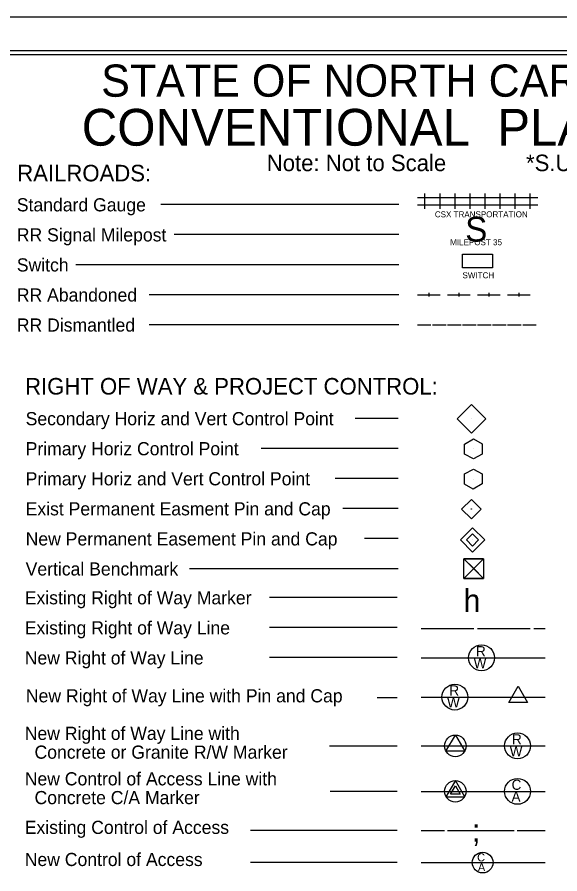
# Model space of a CAD drawing. Extents: x 10000 to 11684, y 10000 to 11100.
# Drawn here: x 10562 to 10923, y 10530 to 11100 of the extents above; entities that cross this region are included whole.
import ezdxf

# ---------------------------------------------------------------- set-up
doc = ezdxf.new("R2010")
doc.units = 0
for name, color, linetype in [('Default', 7, 'Continuous'), ('Prop ROW Permanent Easement CELL', 7, 'Continuous'), ('Sheet Cutting Line CELL', 7, 'Continuous'), ('Sheet Plot Border Inside CELL', 7, 'Continuous'), ('Sheet Plot Border Outside CELL', 7, 'Continuous'), ('Sheet Symbology CELL', 7, 'Continuous')]:
    doc.layers.add(name, color=color, linetype=linetype)

msp = doc.modelspace()

# ---------------------------------------------------------------- linework, layer by layer
at = {"layer": 'Default'}
for p, q in [((10863.87, 10832.65), (10863.87, 10832.65)), ((10865.17, 10812.64), (10865.17, 10812.64)), ((10865.17, 10792.64), (10865.17, 10792.64)), ((10863.9, 10772.61), (10863.9, 10772.61)), ((10865.42, 10733.03), (10865.42, 10733.03))]:
    msp.add_line(p, q, dxfattribs=at)
for points in [[(10854.46, 10832.68), (10863.92, 10842.14), (10873.39, 10832.66), (10863.93, 10823.21)], [(10859.34, 10796.02), (10865.21, 10799.29), (10871.07, 10796.06), (10870.98, 10789.34), (10865.12, 10785.94), (10859.34, 10789.21)], [(10857.4, 10772.61), (10863.9, 10779.1), (10870.39, 10772.61), (10863.9, 10766.11)], [(10858.93, 10739.51), (10871.89, 10739.51), (10871.89, 10726.54), (10858.93, 10726.54)]]:
    msp.add_lwpolyline(points, close=True, dxfattribs=at)
for points in [[(10865.17, 10805.99), (10859.38, 10809.28), (10859.38, 10815.94), (10865.17, 10819.3), (10870.97, 10816.01), (10870.97, 10809.28), (10865.17, 10805.99)], [(10871.89, 10739.51), (10858.93, 10726.54), (10865.41, 10733.02), (10871.89, 10726.54), (10858.93, 10739.51)], [(10865.41, 10733.02), (10871.89, 10739.51), (10858.93, 10739.51), (10865.41, 10733.02)], [(10865.41, 10733.02), (10858.93, 10726.54), (10871.89, 10726.54), (10865.41, 10733.02)]]:
    msp.add_lwpolyline(points, dxfattribs=at)
msp.add_circle((10863.9, 10772.61), 0.126, dxfattribs=at)
at = {"layer": 'Prop ROW Permanent Easement CELL'}
msp.add_line((10864.66, 10752.06), (10864.66, 10752.06), dxfattribs=at)
for points in [[(10864.66, 10760.11), (10872.71, 10752.06), (10864.66, 10744.01), (10856.61, 10752.06)], [(10864.66, 10756.08), (10868.69, 10752.06), (10864.66, 10748.03), (10860.63, 10752.06)]]:
    msp.add_lwpolyline(points, close=True, dxfattribs=at)
at = {"layer": 'Sheet Cutting Line CELL'}
msp.add_line((11684, 11100), (10000, 11100), dxfattribs=at)
at = {"layer": 'Sheet Plot Border Inside CELL'}
msp.add_lwpolyline([(10013, 10022.45), (11679.5, 10022.45), (11679.5, 11077.55), (10013, 11077.55)], close=True, dxfattribs=at)
at = {"layer": 'Sheet Plot Border Outside CELL'}
msp.add_lwpolyline([(10000, 10000), (11684, 10000), (11684, 11100), (10000, 11100)], close=True, dxfattribs=at)
at = {"layer": 'Sheet Symbology CELL'}
for p, q in [((10833, 10972.53), (10833, 10982.53)), ((10843, 10972.53), (10843, 10982.53)), ((10853, 10972.53), (10853, 10982.53)), ((10863, 10972.53), (10863, 10982.53)), ((10873, 10972.53), (10873, 10982.53)), ((10883, 10972.53), (10883, 10982.53)), ((10893, 10972.53), (10893, 10982.53)), ((10903, 10972.53), (10903, 10982.53)), ((10815.61, 10975.27), (10657.19, 10975.27)), ((10828, 10980.03), (10838, 10980.03)), ((10828, 10975.03), (10838, 10975.03)), ((10838, 10980.03), (10848, 10980.03)), ((10838, 10975.03), (10848, 10975.03)), ((10848, 10980.03), (10858, 10980.03)), ((10848, 10975.03), (10858, 10975.03)), ((10858, 10980.03), (10868, 10980.03)), ((10858, 10975.03), (10868, 10975.03)), ((10868, 10980.03), (10878, 10980.03)), ((10868, 10975.03), (10878, 10975.03)), ((10878, 10980.03), (10888, 10980.03)), ((10878, 10975.03), (10888, 10975.03)), ((10888, 10980.03), (10898, 10980.03)), ((10888, 10975.03), (10898, 10975.03)), ((10898, 10980.03), (10908, 10980.03)), ((10898, 10975.03), (10908, 10975.03)), ((10815.61, 10955.27), (10666.06, 10955.27)), ((10815.61, 10935.27), (10600.69, 10935.27)), ((10815.61, 10915.27), (10649.44, 10915.27)), ((10828, 10915.27), (10843, 10915.27)), ((10835.5, 10916.52), (10835.5, 10914.02)), ((10848, 10915.27), (10863, 10915.27)), ((10855.5, 10916.52), (10855.5, 10914.02)), ((10868, 10915.27), (10883, 10915.27)), ((10875.5, 10916.52), (10875.5, 10914.02)), ((10888, 10915.27), (10903, 10915.27)), ((10895.5, 10916.52), (10895.5, 10914.02)), ((10815.61, 10895.27), (10649.44, 10895.27)), ((10815.61, 10895.27), (10649.44, 10895.27)), ((10828, 10895.27), (10837, 10895.27)), ((10838, 10895.27), (10847, 10895.27)), ((10848, 10895.27), (10857, 10895.27)), ((10858, 10895.27), (10867, 10895.27)), ((10868, 10895.27), (10877, 10895.27)), ((10878, 10895.27), (10887, 10895.27)), ((10888, 10895.27), (10897, 10895.27)), ((10898, 10895.27), (10907, 10895.27)), ((10815.06, 10832.98), (10786.51, 10832.98)), ((10815.06, 10812.98), (10724.03, 10812.98)), ((10815.06, 10792.98), (10773.14, 10792.98)), ((10815.06, 10772.98), (10778.36, 10772.98)), ((10815.06, 10752.98), (10792.7, 10752.98)), ((10815.06, 10732.98), (10676.22, 10732.98)), ((10814.47, 10713.79), (10729.53, 10713.79)), ((10814.47, 10693.79), (10729.53, 10693.79)), ((10830.5, 10693.22), (10865.5, 10693.22)), ((10868, 10693.22), (10903, 10693.22)), ((10905.5, 10693.22), (10913, 10693.22)), ((10814.47, 10673.79), (10729.53, 10673.79)), ((10830.5, 10673.67), (10913, 10673.67)), ((10814.47, 10646.94), (10801.22, 10646.94)), ((10830.5, 10647.54), (10913, 10647.54)), ((10894.95, 10647.54), (10894.95, 10647.54)), ((10814.47, 10614.91), (10769.48, 10614.91)), ((10830.5, 10615.04), (10913, 10615.04)), ((10853.2, 10615.04), (10853.2, 10615.04)), ((10814.47, 10584.66), (10769.85, 10584.66)), ((10830.5, 10584.8), (10913, 10584.8)), ((10853.2, 10584.8), (10853.2, 10584.8)), ((10814.47, 10558.72), (10716.92, 10558.72)), ((10830.5, 10558.72), (10845.96, 10558.72)), ((10847.96, 10558.72), (10892.37, 10558.72)), ((10894.37, 10558.72), (10913, 10558.72)), ((10814.47, 10537.37), (10716.92, 10537.37)), ((10830.5, 10537.37), (10913, 10537.37))]:
    msp.add_line(p, q, dxfattribs=at)
for points in [[(11667, 11075), (10167, 11075), (10167, 10026.02), (11667, 10026.02)], [(10858, 10942.23), (10878, 10942.23), (10878, 10933.13), (10858, 10933.13)], [(10888.7, 10643.94), (10894.95, 10654.74), (10901.2, 10643.94)], [(10846.95, 10611.44), (10853.2, 10622.24), (10859.45, 10611.44)], [(10846.95, 10581.2), (10859.45, 10581.2), (10853.2, 10592)], [(10849.93, 10582.92), (10853.2, 10588.56), (10856.47, 10582.92)]]:
    msp.add_lwpolyline(points, close=True, dxfattribs=at)
for centre, radius in [((10870.62, 10673.67), 8.61), ((10852.92, 10647.54), 8.61), ((10853.19, 10615.04), 7.2), ((10894.59, 10615.04), 8.61), ((10894.59, 10584.8), 8.61), ((10853.19, 10584.8), 7.2), ((10871.37, 10537.37), 6.89)]:
    msp.add_circle(centre, radius, dxfattribs=at)

# ---------------------------------------------------------------- texts
for s, height, p in [('STATE OF NORTH CAROLINA, DIVISION OF HIGHWAYS', 21.419, (10617.56, 11047.04)), ('CONVENTIONAL  PLAN SHEET SYMBOLS', 24.4803, (10604.61, 11014.47)), ('RAILROADS:', 11, (10561.72, 10990.72)), ('Standard Gauge', 8.75, (10561.44, 10970.74)), ('S', 16.5, (10859.76, 10950.64)), ('RR Signal Milepost', 8.75, (10561.44, 10950.74)), ('Switch', 8.75, (10561.44, 10930.74)), ('RR Abandoned', 8.75, (10561.44, 10910.74)), ('RR Dismantled', 8.75, (10561.44, 10890.74)), ('RIGHT OF WAY & PROJECT CONTROL:', 11, (10566.93, 10848.87)), ('Secondary Horiz and Vert Control Point', 8.75, (10567.31, 10828.43)), ('Primary Horiz Control Point', 8.75, (10567.31, 10808.43)), ('Primary Horiz and Vert Control Point', 8.75, (10567.31, 10788.43)), ('Exist Permanent Easment Pin and Cap', 8.75, (10567.31, 10768.43)), ('New Permanent Easement Pin and Cap', 8.75, (10567.31, 10748.43)), ('Vertical Benchmark', 8.75, (10567.31, 10728.43)), ('Existing Right of Way Marker', 8.75, (10566.72, 10709.24)), ('h', 15, (10858.68, 10704.22)), ('Existing Right of Way Line', 8.75, (10566.72, 10689.24)), ('New Right of Way Line', 8.75, (10566.72, 10669.24)), ('R', 6.75, (10866.91, 10674.68)), ('W', 6.75, (10865.37, 10666.73)), ('New Right of Way Line with Pin and Cap', 8.75, (10567.48, 10644.02)), ('R', 6.75, (10849.21, 10648.56)), ('W', 6.75, (10847.67, 10640.61)), ('New Right of Way Line with', 8.75, (10566.72, 10619.02)), ('R', 6.75, (10890.89, 10616.06)), ('  Concrete or Granite R/W Marker', 8.75, (10566.72, 10606.52)), ('W', 6.75, (10889.35, 10608.11)), ('New Control of Access Line with', 8.75, (10566.72, 10588.77)), ('C', 6.75, (10890.63, 10585.81)), ('  Concrete C/A Marker', 8.75, (10566.72, 10576.27)), ('A', 6.75, (10890.57, 10577.86)), ('Existing Control of Access', 8.75, (10566.72, 10556.46)), (';', 15, (10864.25, 10551.22)), ('New Control of Access', 8.75, (10566.72, 10535.1)), ('C', 5.4, (10867.71, 10538.18)), ('A', 5.4, (10868.25, 10531.69))]:
    msp.add_text(s, height=height, dxfattribs=at).set_placement(p)
for s, height, p in [('Note: Not to Scale', 11, (10727.74, 10997.51)), ('*S.U.E. = Subsurface Utility Engineering', 11, (10900.22, 10997.51)), ('CSX TRANSPORTATION', 4, (10839.56, 10966.79)), ('MILEPOST 35', 4, (10849.75, 10948.22)), ('SWITCH', 4, (10857.95, 10926.22))]:
    msp.add_text(s, height=height, rotation=360, dxfattribs=at).set_placement(p)

doc.saveas('drawing.dxf')
